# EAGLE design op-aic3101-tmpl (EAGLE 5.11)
PID: 827
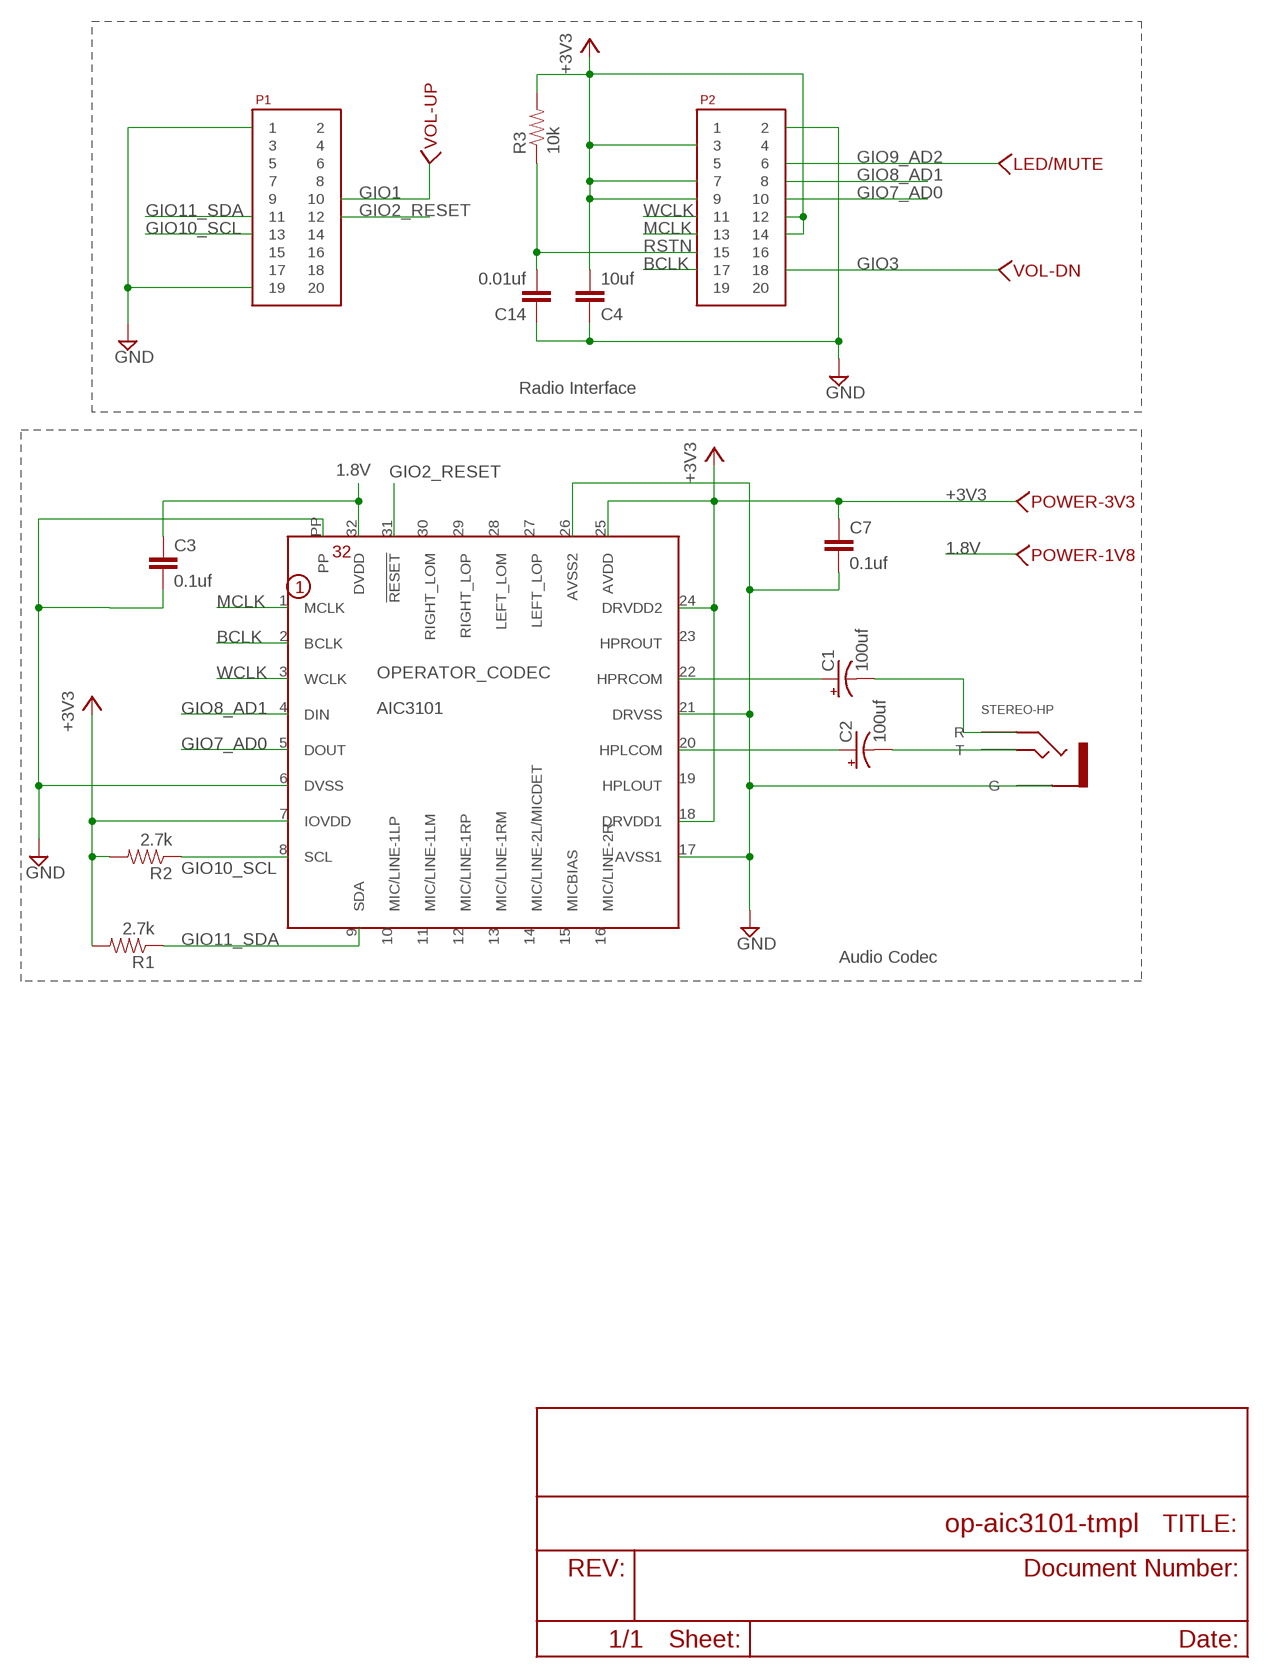
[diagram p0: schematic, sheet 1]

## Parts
C1  100uf  CPOL-USE  [PANASONIC_E]
C2  100uf  CPOL-USE  [PANASONIC_E]
C3  0.1uf  C-EUC1206  [C1206]
C4  10uf  C-EUC1206  [C1206]
C7  0.1uf  C-EUC1206  [C1206]
C14  0.01uf  C-EUC1206  [C1206]
LED/MUTE  WIREPAD-SMD-SMALL-NAMED  [WIREPAD-SMD-SMALL]
OPERATOR_CODEC  AIC3101  [32QFN-AIC3101]
P1  SAMTEC-10X2  [SAMTEC-10X2]
P2  SAMTEC-10X2  [SAMTEC-10X2]
POWER-1V8  WIREPAD-SMD-SMALL-NAMED  [WIREPAD-SMD-SMALL]
POWER-3V3  WIREPAD-SMD-SMALL-NAMED  [WIREPAD-SMD-SMALL]
R1  2.7k  RESISTOR1206  [1206]
R2  2.7k  RESISTOR1206  [1206]
R3  10k  RESISTOR  [0805]
STEREO-HP  HEADPHONE-STEREO-NO-SWITCH  [HEADPHONE-STEREO-NO-SWITCH]
VOL-DN  WIREPAD-SMD-SMALL-NAMED  [WIREPAD-SMD-SMALL]
VOL-UP  WIREPAD-SMD-SMALL-NAMED  [WIREPAD-SMD-SMALL]

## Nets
1.8V: C3.1 OPERATOR_CODEC.32(DVDD) POWER-1V8.1
+3V3: C4.2 C7.1 OPERATOR_CODEC.7(IOVDD) OPERATOR_CODEC.18(DRVDD1) OPERATOR_CODEC.24(DRVDD2) OPERATOR_CODEC.25(AVDD) P2.3 P2.7 P2.9 P2.12 P2.14 POWER-3V3.1 R1.2 R2.2 R3.2
BCLK: OPERATOR_CODEC.2(BCLK) P2.17
GIO1: P1.10 VOL-UP.1
GIO2_RESET: OPERATOR_CODEC.31(!RESET) P1.12
GIO3: P2.18 VOL-DN.1
GIO7_AD0: OPERATOR_CODEC.5(DOUT) P2.10
GIO8_AD1: OPERATOR_CODEC.4(DIN) P2.8
GIO9_AD2: LED/MUTE.1 P2.6
GIO10_SCL: OPERATOR_CODEC.8(SCL) P1.13 R2.1
GIO11_SDA: OPERATOR_CODEC.9(SDA) P1.11 R1.1
GND: C3.2 C4.1 C7.2 C14.1 OPERATOR_CODEC.6(DVSS) OPERATOR_CODEC.17(AVSS1) OPERATOR_CODEC.21(DRVSS) OPERATOR_CODEC.26(AVSS2) OPERATOR_CODEC.PP P1.1 P1.19 P2.2 STEREO-HP.G
MCLK: OPERATOR_CODEC.1(MCLK) P2.13
N$5: C1.+ OPERATOR_CODEC.22(HPRCOM)
N$6: C2.+ OPERATOR_CODEC.20(HPLCOM)
N$7: C2.- STEREO-HP.T
N$8: C1.- STEREO-HP.R
RSTN: C14.2 P2.15 R3.1
WCLK: OPERATOR_CODEC.3(WCLK) P2.11
Unconnected: OPERATOR_CODEC.10(MIC/LINE-1LP) OPERATOR_CODEC.11(MIC/LINE-1LM) OPERATOR_CODEC.12(MIC/LINE-1RP) OPERATOR_CODEC.13(MIC/LINE-1RM) OPERATOR_CODEC.14(MIC/LINE-2L/MICDET) OPERATOR_CODEC.15(MICBIAS) OPERATOR_CODEC.16(MIC/LINE-2R) OPERATOR_CODEC.19(HPLOUT) OPERATOR_CODEC.23(HPROUT) OPERATOR_CODEC.27(LEFT_LOP) OPERATOR_CODEC.28(LEFT_LOM) OPERATOR_CODEC.29(RIGHT_LOP) OPERATOR_CODEC.30(RIGHT_LOM) P1.2 P1.3 P1.4 P1.5 P1.6 P1.7 P1.8 P1.9 P1.14 P1.15 P1.16 P1.17 P1.18 P1.20 P2.1 P2.4 P2.5 P2.16 P2.19 P2.20

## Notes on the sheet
- Radio Interface
- Audio Codec

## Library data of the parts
C1 C2 = rcl:CPOL-US: POLARIZED CAPACITOR, American symbol
C3 C4 C7 C14 = rcl:C-EU: CAPACITOR, European symbol
LED/MUTE POWER-1V8 POWER-3V3 VOL-DN VOL-UP = trl:WIREPAD-SMD-SMALL-NAMED
OPERATOR_CODEC = trl:AIC3101
P1 P2 = trl:SAMTEC-10X2
R1-R3 = SparkFun:RESISTOR: Resistor
STEREO-HP = trl:HEADPHONE-STEREO-NO-SWITCH

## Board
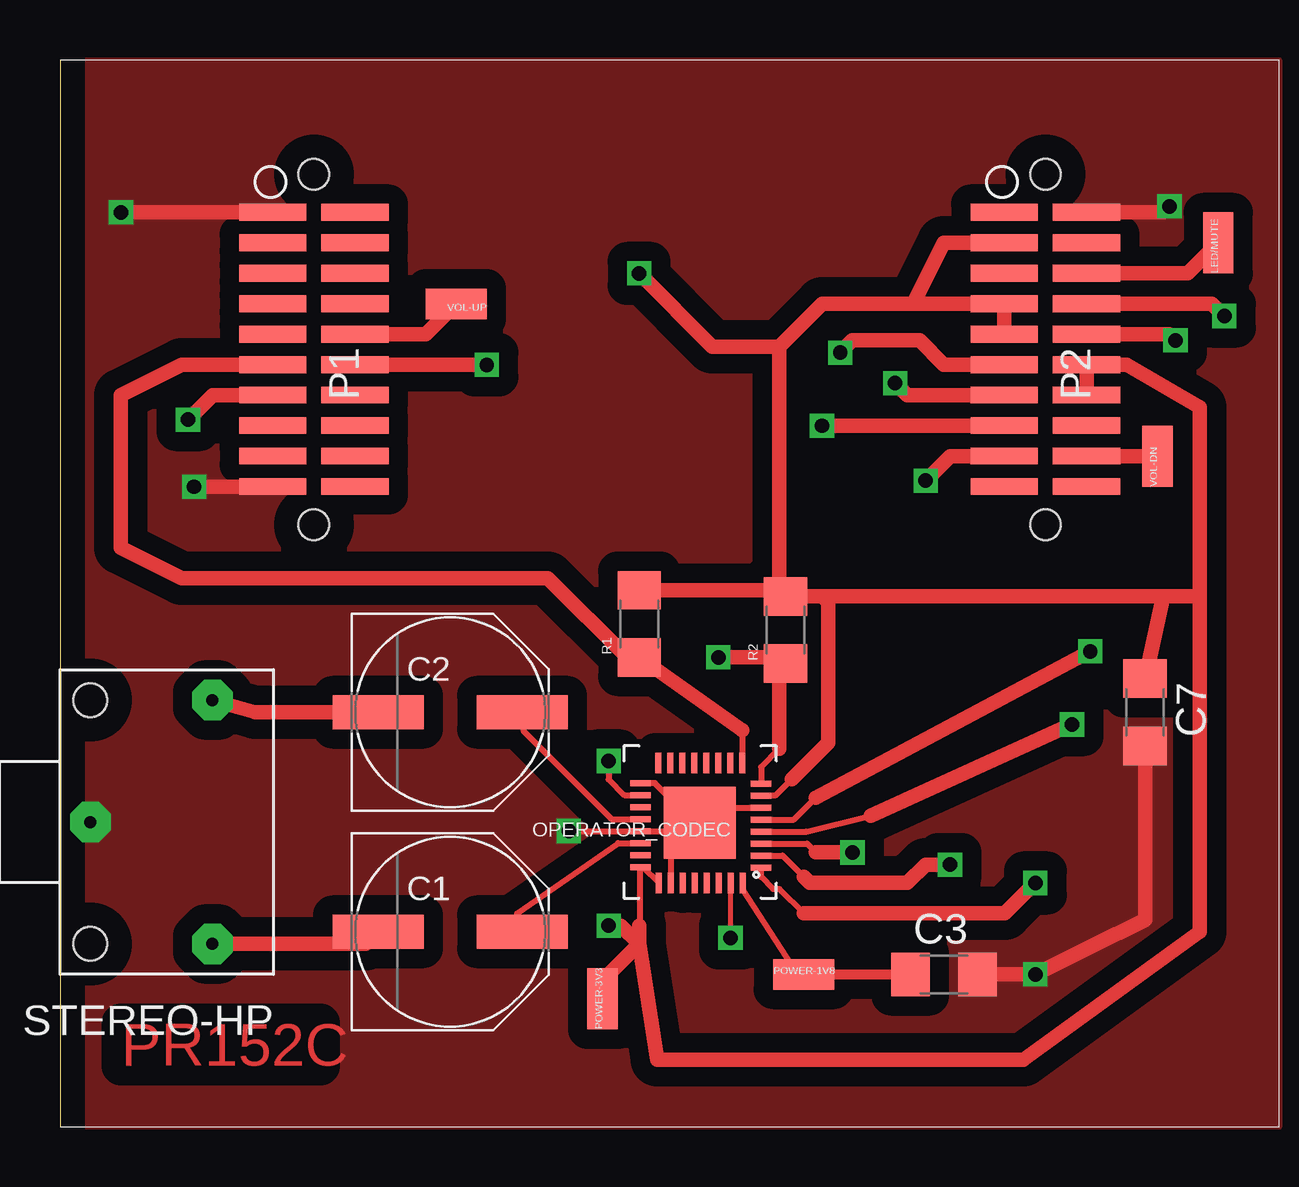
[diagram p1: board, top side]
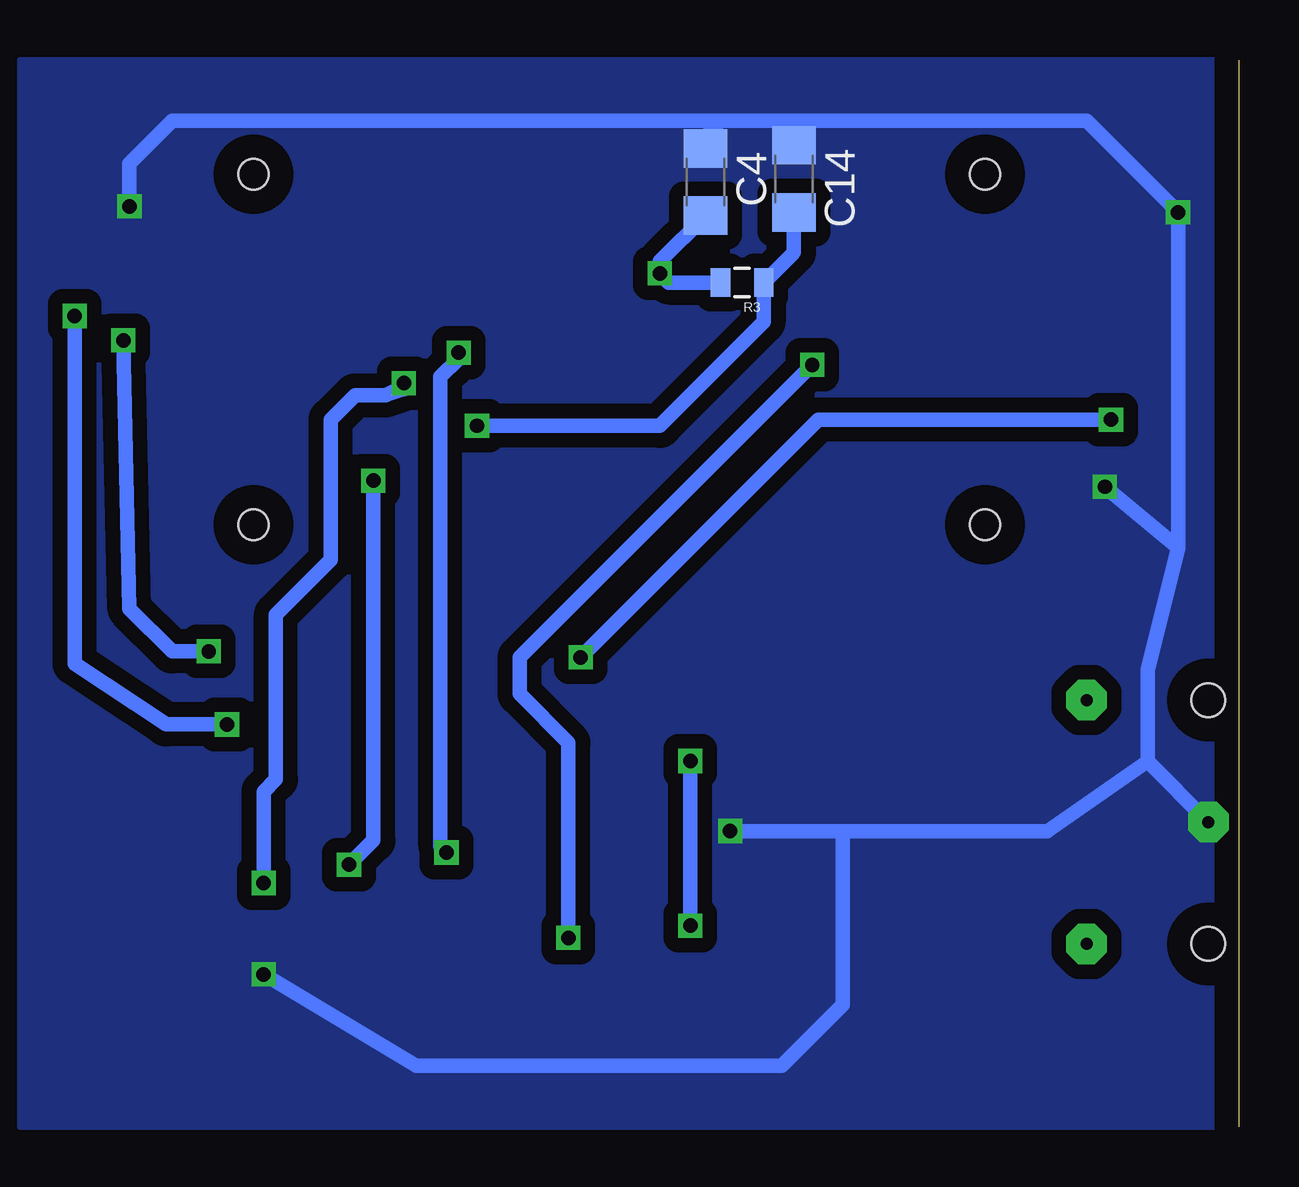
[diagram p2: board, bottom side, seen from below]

Size 0 x 44.45 mm. Coordinates in mm from the lower left corner, seen from the top.
Outline: 0,44.45 0,0
Copper layers (1*16): Top 0.035mm / dielectric 1.5mm / Bottom 0.035mm
Design rules "default": minimum track width 10mil, minimum drill 24mil, track to track 8mil, track to pad 8mil, pad to pad 8mil, via to via 8mil, smd to smd 8mil, copper to edge 40mil, drill to drill 8mil, minimum pad ring 10mil, minimum via ring 8mil, stop-mask expansion 4mil, vias tented up to drill 0mil, thermal gap 10mil

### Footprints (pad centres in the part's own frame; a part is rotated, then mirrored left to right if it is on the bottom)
PANASONIC_E = smd 3.8 x 1.4: + 3,0; - -3,0
C1206 = smd 1.6 x 1.8: 1 -1.4,0; 2 1.4,0
WIREPAD-SMD-SMALL = smd 2.54 x 1.27: 1 0,0
32QFN-AIC3101 = smd 0.85 x 0.25: 1 -2.54,1.905; 2 -2.54,1.405; 3 -2.54,0.905; 4 -2.54,0.405; 5 -2.54,-0.095; 6 -2.54,-0.595; 7 -2.54,-1.095; 8 -2.54,-1.595; 17 2.49,-1.625; 18 2.49,-1.125; 19 2.49,-0.625; 20 2.49,-0.125; 21 2.49,0.375; 22 2.49,0.875; 23 2.49,1.375; 24 2.49,1.875 | smd 0.25 x 0.85: 9 -1.76,-2.465; 10 -1.26,-2.465; 11 -0.76,-2.465; 12 -0.26,-2.465; 13 0.24,-2.465; 14 0.74,-2.465; 15 1.24,-2.465; 16 1.74,-2.465; 25 1.72,2.535; 26 1.22,2.535; 27 0.72,2.535; 28 0.22,2.535; 29 -0.28,2.535; 30 -0.78,2.535; 31 -1.28,2.535; 32 -1.78,2.535 | smd 3 x 3: PP 0.02,0.025
SAMTEC-10X2 = smd 0.7 x 2.8: 1 -6.358,-1.296; 2 -6.358,2.134; 3 -5.088,-1.296; 4 -5.088,2.134; 5 -3.818,-1.296; 6 -3.818,2.134; 7 -2.548,-1.296; 8 -2.548,2.134; 9 -1.278,-1.296; 10 -1.278,2.134; 11 -0.008,-1.296; 12 -0.008,2.134; 13 1.262,-1.296; 14 1.262,2.134; 15 2.532,-1.296; 16 2.532,2.134; 17 3.802,-1.296; 18 3.802,2.134; 19 5.072,-1.296; 20 5.072,2.134 | hole 1.27: -7.938,0.42; 6.66,0.42
1206 = smd 1.6 x 1.8: 1 -1.4,0; 2 1.4,0
0805 = smd 0.8 x 1.2: 1 -0.9,0; 2 0.9,0
HEADPHONE-STEREO-NO-SWITCH = drill 0.5 pad 1.676 octagon: G 5.08,0; R 0,5.08; T 0,-5.08 | hole 1.4: 5.08,5.08; 5.08,-5.08

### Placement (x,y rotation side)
C1  16.26,8.13 0 top  (outside the outline)
C2  16.26,17.27 0 top  (outside the outline)
C3  36.83,6.35 0 top  (outside the outline)
C4  22.23,39.37 270 bottom  (outside the outline)
C7  45.21,17.27 270 top  (outside the outline)
C14  18.54,39.5 270 bottom  (outside the outline)
LED/MUTE  48.26,36.83 90 top  (outside the outline)
OPERATOR_CODEC  26.67,12.7 180 top  (outside the outline)
P1  10.16,31.75 270 top  (outside the outline)
P2  40.64,31.75 270 top  (outside the outline)
POWER-1V8  30.99,6.35 0 top  (outside the outline)
POWER-3V3  22.61,5.33 90 top  (outside the outline)
R1  24.13,20.95 90 top  (outside the outline)
R2  30.23,20.7 90 top  (outside the outline)
R3  20.7,35.18 180 bottom  (outside the outline)
STEREO-HP  6.35,12.7 180 top
VOL-DN  45.72,27.94 90 top  (outside the outline)
VOL-UP  16.51,34.29 180 top  (outside the outline)

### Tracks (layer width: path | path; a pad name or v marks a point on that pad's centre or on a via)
1.8V
  Top 0.254: OPERATOR_CODEC.32 28.45,9.9 30.73,6.35 POWER-1V8.1
  Top 0.406: POWER-1V8.1 C3.1
+3V3  (via drill 0.6)
  Top 0.254: OPERATOR_CODEC.25 24.29,10.82 OPERATOR_CODEC.24 24.18,8.43 24.13,8.38 | OPERATOR_CODEC.18 23.51,13.82 22.86,14.48 v22.86,15.24 | OPERATOR_CODEC.7 29.8,13.79 30.48,14.48
  Top 0.61: P2.14 P2.12 42.78,31.75 44.45,31.75 47.5,29.97 47.5,22.1 | 29.97,22.36 R1.2 | 29.97,22.36 R2.2 31.75,22.1 | 29.97,22.36 29.97,32.51 | 29.97,32.51 31.75,34.29 P2.7 | 29.97,32.51 27.18,32.51 v24.13,35.56 | 45.97,22.1 45.98,22.1 47.5,22.1 | 45.97,22.1 31.75,22.1 | P2.7 P2.9 | P2.7 35.55,34.3 36.83,36.83 P2.3 | 24.13,7.62 24.89,2.79 40.13,2.79 47.5,8.13 47.5,22.1 | 30.48,14.48 32,16 32,21.85 31.75,22.1 | 45.97,22.1 C7.1 | POWER-3V3.1 22.61,6.1 24.13,7.62 | v22.86,8.38 23.37,8.38 24.13,7.62 | 24.13,7.62 24.13,8.38
  Bottom 0.61: C4.2 24.13,36.06 v24.13,35.56 23.75,35.18 R3.2 | v22.86,8.38 v22.86,15.24
BCLK  (via drill 0.6 pad 0.61)
  Top 0.254: OPERATOR_CODEC.2 30.11,11.29 30.99,10.41
  Top 0.61: P2.17 37.09,27.95 v36.07,26.92 | v37.08,10.92 36.07,10.92 35.31,10.16 31.24,10.16 30.99,10.41
  Bottom 0.61: v36.07,26.92 36.07,11.94 v37.08,10.92
GIO1
  Top 0.61: P1.10 15.25,33.03 VOL-UP.1
GIO2_RESET  (via drill 0.6)
  Top 0.2: 27.95,7.88 OPERATOR_CODEC.31
  Top 0.254: v27.94,7.87 27.95,7.88
  Top 0.61: v17.78,31.75 12.3,31.75 P1.12
  Bottom 0.61: v27.94,7.87 27.94,16 29.97,18.03 29.97,19.56 v17.78,31.75
GIO3
  Top 0.61: P2.18 VOL-DN.1
GIO7_AD0  (via drill 0.6 pad 0.61)
  Top 0.254: OPERATOR_CODEC.5 30.57,12.79 31.5,13.72
  Top 0.61: P2.10 46.22,33.03 v46.48,32.77 | 31.5,13.72 v42.93,19.81
  Bottom 0.61: v46.48,32.77 46.23,21.59 44.45,19.81 v42.93,19.81
GIO8_AD1  (via drill 0.6 pad 0.61)
  Top 0.254: OPERATOR_CODEC.4 31.09,12.29 33.78,12.95
  Top 0.61: P2.8 48,34.3 v48.51,33.78 | 33.78,12.95 v42.16,16.76
  Bottom 0.61: v42.16,16.76 44.7,16.76 48.51,19.3 v48.51,33.78
GIO9_AD2
  Top 0.61: P2.6 47,35.57 LED/MUTE.1
GIO10_SCL  (via drill 0.6)
  Top 0.254: OPERATOR_CODEC.8 29.21,14.99 29.97,15.75
  Top 0.61: 29.97,15.75 29.97,19.05 R2.1 29.97,19.56 v27.43,19.56 | P1.13 6.36,30.49 v5.33,29.46
  Bottom 0.61: v5.33,29.46 17.53,29.46 v27.43,19.56
GIO11_SDA
  Top 0.254: 28.43,16.52 OPERATOR_CODEC.9
  Top 0.61: 28.43,16.52 R1.1 23.62,19.55 20.32,22.86 5.08,22.86 2.54,24.13 2.54,30.48 5.08,31.75 P1.11
GND  (via drill 0.6, 0.6 pad 0.61)
  Top 0.254: v46.23,38.35 45.98,38.11 | v21.2,12.32 OPERATOR_CODEC.21 25.91,12.32 | 25.91,12.32 26.3,12.32 OPERATOR_CODEC.PP | OPERATOR_CODEC.17 24.79,14.32 25.91,13.21 26.12,13.21 OPERATOR_CODEC.PP | OPERATOR_CODEC.26 25.45,11.87 25.91,12.32 | OPERATOR_CODEC.6 26.76,13.29 26.67,13.21 26.67,12.7 OPERATOR_CODEC.PP
  Top 0.61: P1.1 6.34,38.11 v2.54,38.1 | 45.98,38.11 P2.2 | P1.19 v5.6,26.68 v5.59,26.67 | C7.2 45.21,8.64 v40.64,6.35 C3.2
  Bottom 0.254: 17.78,41.91 18.54,41.15
  Bottom 0.61: C4.1 22.1,40.9 22.1,41.4 21.59,41.91 | v46.23,38.35 46.23,40.13 44.45,41.91 21.59,41.91 | 21.59,41.91 17.78,41.91 6.35,41.91 v2.54,38.1 2.54,24.13 | 18.54,41.15 C14.1 | 3.81,15.24 3.81,19.05 2.54,24.13 | 2.54,24.13 v5.59,26.67 | 16.51,12.32 8,12.32 3.81,15.24 | 16.51,12.32 v21.2,12.32 | v40.64,6.35 34.29,2.54 19.05,2.54 16.51,5.08 16.51,12.32 | STEREO-HP.G 3.81,15.24
  pour Bottom (isolate 0.61, no thermals): 0,44.45 50.8,44.45 50.8,0 0,0
  pour Top (isolate 0.813, no thermals): 0,44.45 50.8,44.45 50.8,0 0,0
MCLK  (via drill 0.6 pad 0.61)
  Top 0.254: 29.21,10.67 OPERATOR_CODEC.1 29.21,10.41 29.72,9.91 29.97,9.91 30.99,8.89
  Top 0.61: 30.99,8.89 39.37,8.89 v40.64,10.16 | P2.13 35.3,30.49 v34.8,30.99
  Bottom 0.61: v40.64,10.16 40.64,13.97 40.13,14.48 40.13,21.34 37.85,23.62 37.85,29.46 36.83,30.48 35.56,30.48 | 35.56,30.48 35.05,30.73 v34.8,30.99 34.8,30.73 35.56,30.48
N$5
  Top 0.254: OPERATOR_CODEC.22 23.25,11.82 19.05,8.89 19.05,8.33 C1.+
N$6
  Top 0.254: OPERATOR_CODEC.20 22.99,12.82 19.3,16.51 19.3,17.22 C2.+
N$7
  Top 0.61: C2.- 8.13,17.27 STEREO-HP.T
N$8
  Top 0.61: STEREO-HP.R 12.75,7.62 C1.-
RSTN  (via drill 0.6)
  Top 0.61: P2.15 35.57,29.22 v31.75,29.21
  Bottom 0.254: 18.6,36.38 18.54,36.44
  Bottom 0.61: 18.54,36.44 C14.2 | 18.6,36.38 R3.1 19.8,33.54 24.13,29.21 v31.75,29.21
WCLK  (via drill 0.6 pad 0.61)
  Top 0.254: OPERATOR_CODEC.3 31.13,11.79 31.5,11.43
  Top 0.61: P2.11 36.82,31.76 35.81,32.77 33.02,32.77 v32.51,32.26 | 31.5,11.43 v33.02,11.43
  Bottom 0.61: v32.51,32.26 32.51,32 33.27,31.24 33.27,11.68 v33.02,11.43

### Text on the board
Top: PR152C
